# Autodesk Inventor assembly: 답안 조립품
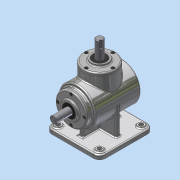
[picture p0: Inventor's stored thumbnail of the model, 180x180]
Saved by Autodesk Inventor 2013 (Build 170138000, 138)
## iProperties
Created: 2015-07
Part Number: 답안 조립품
Document SubType Name: Assembly
Designer: dgall
Author: dgall
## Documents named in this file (14)
- C:\Users\dgall\Desktop\450705V1012\답안 조립품.iam
- C:\Users\dgall\Desktop\450705V1012\본체.ipt
- C:\Users\dgall\Desktop\450705V1012\커버.ipt
- C:\Users\dgall\Desktop\450705V1012\메인 축.ipt
- 메인 축.ipt
- C:\Users\dgall\Desktop\450705V1012\오일실.ipt
- C:\Users\dgall\Desktop\450705V1012\키 5x5.ipt
- C:\Users\dgall\Desktop\450705V1012\메인 베벨기어.ipt
- C:\Users\dgall\Desktop\450705V1012\베어링 6203.ipt
- C:\Users\dgall\Desktop\450705V1012\서브 축.ipt
- 서브 축.ipt
- C:\Users\dgall\Desktop\450705V1012\서브 베벨기어.ipt
- C:\Users\dgall\Desktop\450705V1012\키 4x4.ipt
- C:\Users\dgall\Desktop\450705V1012\M4.ipt
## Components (8 placed, 1 different names)
1. M4:1
2. M4:2
3. M4:3
4. M4:4
5. M4:5
6. M4:6
7. M4:7
8. M4:8
